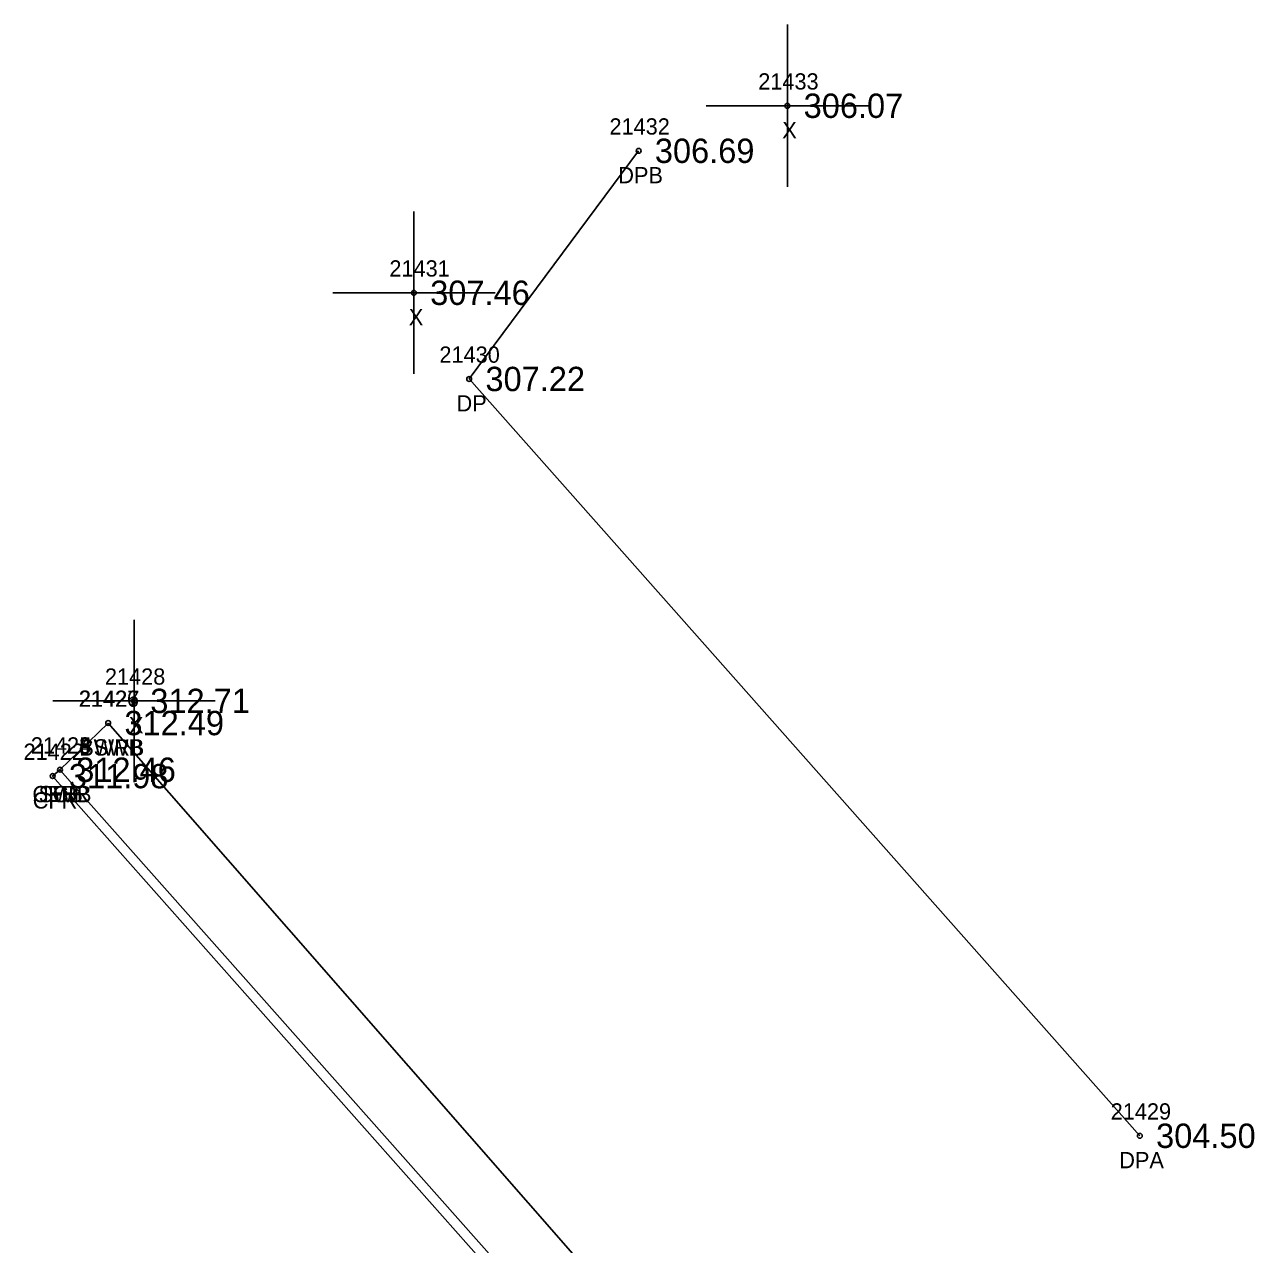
# Model space of a CAD drawing. Extents: x 1970242 to 1971082, y 803104 to 803947.
# Drawn here: x 1970348.9 to 1970424.7, y 803871.8 to 803947 of the extents above; entities that cross this region are included whole.
import ezdxf

# ---------------------------------------------------------------- set-up
doc = ezdxf.new("R2010")
doc.units = 0
for name, color, linetype in [('RD_DTM_BkLn2', 7, 'Continuous'), ('RD_EX_Conc', 7, 'Continuous'), ('RD_EX_Conc_txCode', 7, 'Continuous'), ('RD_EX_Driveway', 7, 'Continuous'), ('RD_EX_Driveway_txCode', 7, 'Continuous'), ('RD_EX_Misc', 7, 'Continuous'), ('RD_EX_Misc_txCode', 7, 'Continuous'), ('RD_EX_TX_Conc_ELEV', 7, 'Continuous'), ('RD_EX_TX_Driveway_ELEV', 7, 'Continuous'), ('RD_EX_TX_Misc_ELEV', 7, 'Continuous'), ('RD_SMD_Locator', 7, 'Continuous')]:
    doc.layers.add(name, color=color, linetype=linetype)

msp = doc.modelspace()

# ---------------------------------------------------------------- linework, layer by layer
at = {"layer": 'RD_DTM_BkLn2'}
msp.add_lwpolyline([(1970409.39, 803835.518), (1970397.172, 803849.109), (1970388.059, 803859.443), (1970351.127, 803901.087)], dxfattribs=at)
at = {"layer": 'RD_EX_Conc'}
msp.add_line((1970390.791, 803862.045), (1970354.096, 803903.963), dxfattribs=at)
for points in [[(1970390.791, 803862.045), (1970388.059, 803859.443), (1970351.127, 803901.087), (1970354.096, 803903.963)], [(1970387.502, 803859.121), (1970350.674, 803900.696), (1970351.127, 803901.087)]]:
    msp.add_lwpolyline(points, dxfattribs=at)
at = {"layer": 'RD_EX_Driveway'}
msp.add_lwpolyline([(1970417.645, 803878.539), (1970376.334, 803925.159), (1970386.77, 803939.214)], dxfattribs=at)
at = {"layer": 'RD_EX_Misc'}
for p, q in [((1970395.934, 803936.988), (1970395.934, 803946.988)), ((1970390.934, 803941.988), (1970400.934, 803941.988)), ((1970372.93, 803925.468), (1970372.93, 803935.468)), ((1970367.93, 803930.468), (1970377.93, 803930.468)), ((1970355.689, 803900.329), (1970355.689, 803910.329)), ((1970350.689, 803905.329), (1970360.689, 803905.329))]:
    msp.add_line(p, q, dxfattribs=at)
at = {"layer": 'RD_SMD_Locator'}
for centre in [(1970395.934, 803941.988), (1970386.77, 803939.214), (1970372.93, 803930.468), (1970376.334, 803925.159), (1970355.689, 803905.329), (1970354.096, 803903.963), (1970354.096, 803903.963), (1970351.127, 803901.087), (1970351.127, 803901.087), (1970351.127, 803901.087), (1970350.674, 803900.696), (1970417.645, 803878.539)]:
    msp.add_circle(centre, 0.15, dxfattribs=at)

# ---------------------------------------------------------------- texts
at = {"layer": 'RD_EX_Conc_txCode'}
for s, p in [('21426', (1970352.277, 803904.963)), ('21427', (1970352.301, 803904.963)), ('21422', (1970348.879, 803901.696)), ('21423', (1970349.331, 803902.087)), ('21424', (1970349.331, 803902.087)), ('21425', (1970349.331, 803902.087)), ('SWRB', (1970352.308, 803901.963)), ('BSWB', (1970352.308, 803901.963)), ('CFRB', (1970349.426, 803899.087)), ('CFR', (1970349.446, 803898.696)), ('SWR', (1970349.812, 803899.087)), ('TCB', (1970349.859, 803899.087))]:
    msp.add_text(s, height=1, dxfattribs=at).set_placement(p)
at = {"layer": 'RD_EX_Driveway_txCode'}
for s, p in [('21432', (1970384.974, 803940.214)), ('DPB', (1970385.518, 803937.214)), ('21430', (1970374.499, 803926.159)), ('DP', (1970375.554, 803923.159)), ('21429', (1970415.85, 803879.539)), ('DPA', (1970416.377, 803876.539))]:
    msp.add_text(s, height=1, dxfattribs=at).set_placement(p)
at = {"layer": 'RD_EX_Misc_txCode'}
for s, p in [('21433', (1970394.139, 803942.988)), ('X', (1970395.619, 803939.988)), ('21431', (1970371.418, 803931.468)), ('X', (1970372.615, 803928.468)), ('21428', (1970353.894, 803906.329)), ('X', (1970355.374, 803903.329))]:
    msp.add_text(s, height=1, dxfattribs=at).set_placement(p)
at = {"layer": 'RD_EX_TX_Conc_ELEV'}
for s, p in [('312.49', (1970355.096, 803903.213)), ('312.49', (1970355.096, 803903.213)), ('311.98', (1970351.674, 803899.946)), ('312.46', (1970352.127, 803900.337)), ('312.46', (1970352.127, 803900.337)), ('312.46', (1970352.127, 803900.337))]:
    msp.add_text(s, height=1.5, dxfattribs=at).set_placement(p)
at = {"layer": 'RD_EX_TX_Driveway_ELEV'}
for s, p in [('306.69', (1970387.77, 803938.464)), ('307.22', (1970377.334, 803924.409)), ('304.50', (1970418.645, 803877.789))]:
    msp.add_text(s, height=1.5, dxfattribs=at).set_placement(p)
at = {"layer": 'RD_EX_TX_Misc_ELEV'}
for s, p in [('306.07', (1970396.934, 803941.238)), ('307.46', (1970373.93, 803929.718)), ('312.71', (1970356.689, 803904.579))]:
    msp.add_text(s, height=1.5, dxfattribs=at).set_placement(p)

doc.saveas('drawing.dxf')
